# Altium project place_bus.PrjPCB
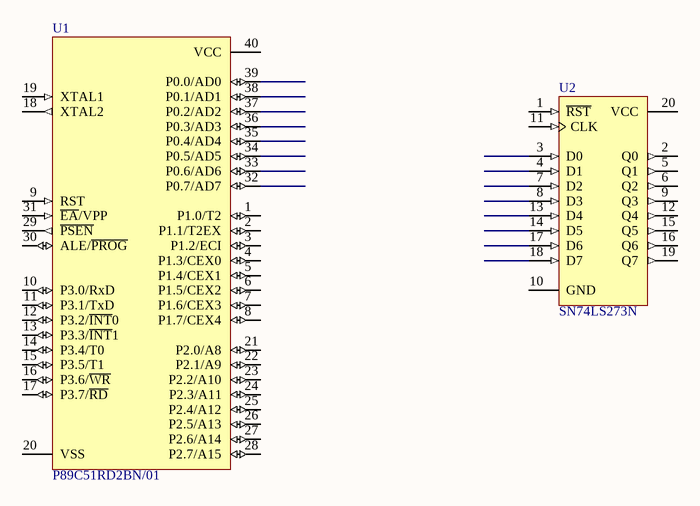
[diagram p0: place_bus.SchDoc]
1 sheet, 2 parts. Net scope: global (net labels, ports and power ports of the same name join across sheets).

## Sheet place_bus.SchDoc
size A4

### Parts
U1  P89C51RD2BN/01  [SOT129-1]
U2  SN74LS273N  [N020]

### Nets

Not connected (* = marked no-connect by the designer): U1 1(P1.0/T2) 2(P1.1/T2EX) 3(P1.2/ECI) 4(P1.3/CEX0) 5(P1.4/CEX1) 6(P1.5/CEX2) 7(P1.6/CEX3) 8(P1.7/CEX4) 9(RST) 10(P3.0/RxD) 11(P3.1/TxD) 12(P3.2/~{INT}0) 13(P3.3/~{INT}1) 14(P3.4/T0) 15(P3.5/T1) 16(P3.6/~{WR}) 17(P3.7/~{RD}) 18(XTAL2) 19(XTAL1) 20(VSS) 21(P2.0/A8) 22(P2.1/A9) 23(P2.2/A10) 24(P2.3/A11) 25(P2.4/A12) 26(P2.5/A13) 27(P2.6/A14) 28(P2.7/A15) 29(~{PSEN}) 30(ALE/~{PROG}) 31(~{EA}/VPP) 32(P0.7/AD7) 33(P0.6/AD6) 34(P0.5/AD5) 35(P0.4/AD4) 36(P0.3/AD3) 37(P0.2/AD2) 38(P0.1/AD1) 39(P0.0/AD0) 40(VCC); U2 1(~{RST}) 2(Q0) 3(D0) 4(D1) 5(Q1) 6(Q2) 7(D2) 8(D3) 9(Q3) 10(GND) 11(CLK) 12(Q4) 13(D4) 14(D5) 15(Q5) 16(Q6) 17(D6) 18(D7) 19(Q7) 20(VCC)

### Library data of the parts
U1 = P89C51RD2BN/01: 80C51 8-Bit Flash Microcontroller Family, 64 kB ISP/IAP Flash with 1 kB RAM.
U2 = SN74LS273N: Octal D-Type Flip-Flop with Clear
